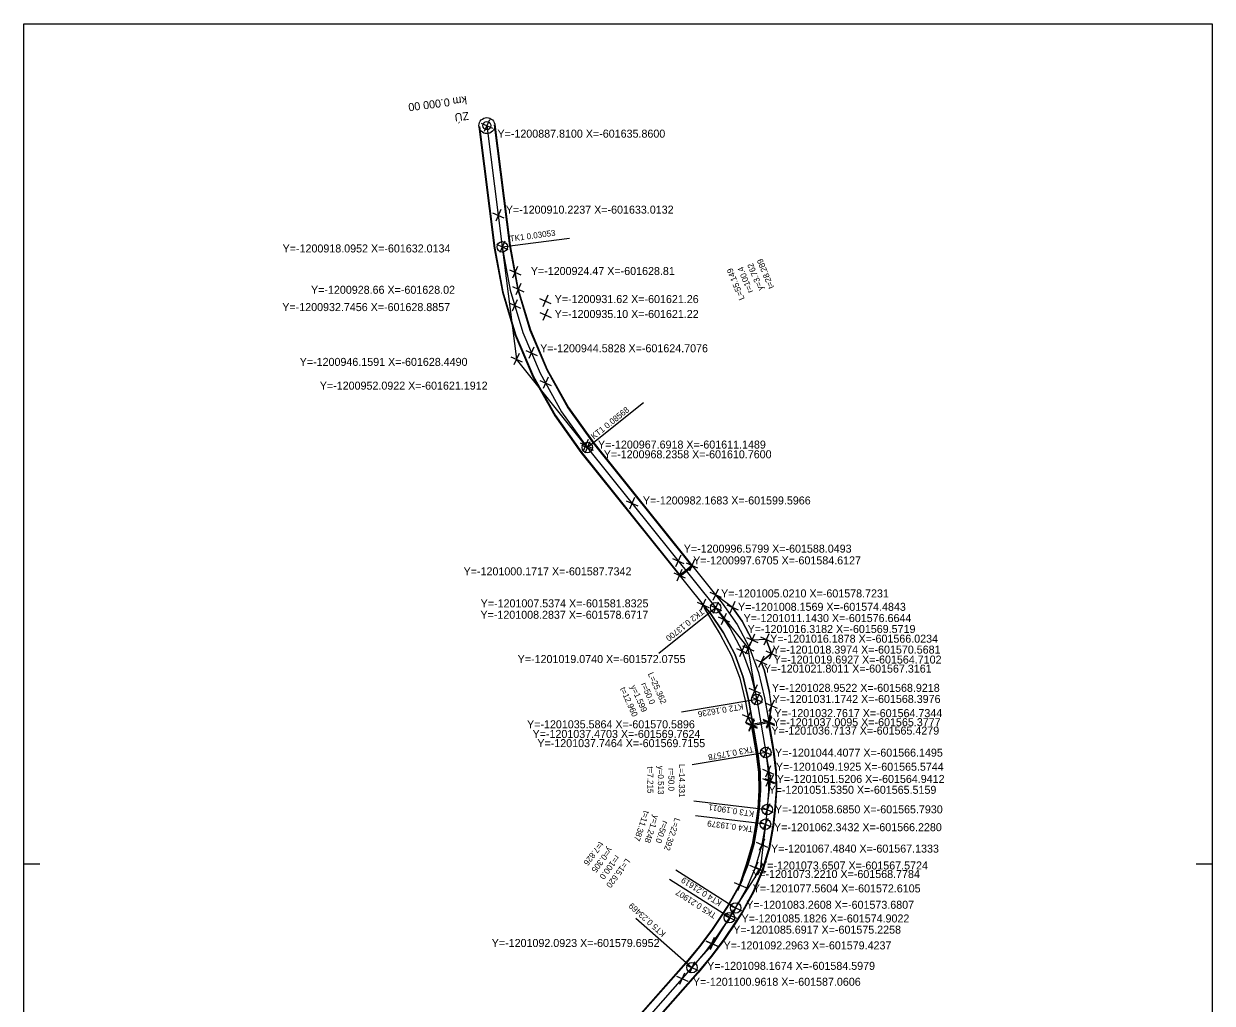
# Model space of a CAD drawing. Extents: x -601752 to -601455, y -1201912 to -1200862.
# Drawn here: x -601751.6 to -601454.6, y -1201107.1 to -1200862.4 of the extents above; entities that cross this region are included whole.
import ezdxf

# ---------------------------------------------------------------- set-up
doc = ezdxf.new("R2010")
doc.units = 0
for name, color, linetype in [('g_vytyceni oblouky', 7, 'Continuous'), ('g_vytyceni prejezd', 7, 'Continuous'), ('g_vytyceni příčné', 7, 'Continuous'), ('q_vytyceni prahy souradnice', 7, 'Continuous'), ('u_návrh', 7, 'Continuous'), ('u_oblouky', 7, 'Continuous'), ('u_osa', 7, 'Continuous'), ('u_popis', 7, 'Continuous'), ('u_popis oblouky', 7, 'Continuous'), ('u_rozšíření v obloucích', 7, 'Continuous'), ('u_staniceni', 7, 'Continuous'), ('x_rám', 7, 'Continuous')]:
    doc.layers.add(name, color=color, linetype=linetype)

msp = doc.modelspace()

# ---------------------------------------------------------------- linework, layer by layer
at = {"layer": 'g_vytyceni oblouky'}
for p, q in [((-601633.44, -1200917.46), (-601630.58, -1200918.73)), ((-601631.38, -1200916.67), (-601632.65, -1200919.52)), ((-601624.08, -1200943.15), (-601625.34, -1200946.01)), ((-601629.88, -1200945.53), (-601627.02, -1200946.79)), ((-601627.82, -1200944.73), (-601629.08, -1200947.59)), ((-601626.14, -1200943.95), (-601623.28, -1200945.22)), ((-601610.13, -1200966.81), (-601611.39, -1200969.66)), ((-601612.19, -1200967.6), (-601609.33, -1200968.87)), ((-601580.1, -1201007.65), (-601577.24, -1201008.92)), ((-601578.04, -1201006.85), (-601579.3, -1201009.71)), ((-601569.94, -1201016.97), (-601571.2, -1201019.83)), ((-601573.5, -1201018.44), (-601570.65, -1201019.71)), ((-601571.44, -1201017.65), (-601572.71, -1201020.5)), ((-601572, -1201017.76), (-601569.14, -1201019.03)), ((-601569.83, -1201030.54), (-601566.97, -1201031.81)), ((-601567.77, -1201029.75), (-601569.03, -1201032.6)), ((-601567.58, -1201043.78), (-601564.72, -1201045.04)), ((-601565.52, -1201042.98), (-601566.78, -1201045.84)), ((-601564.88, -1201050.11), (-601566.15, -1201052.96)), ((-601564.31, -1201050.09), (-601565.57, -1201052.95)), ((-601566.94, -1201050.9), (-601564.09, -1201052.17)), ((-601566.37, -1201050.89), (-601563.51, -1201052.15)), ((-601567.22, -1201058.05), (-601564.36, -1201059.32)), ((-601565.16, -1201057.26), (-601566.43, -1201060.11)), ((-601567.66, -1201061.71), (-601564.8, -1201062.98)), ((-601565.6, -1201060.91), (-601566.86, -1201063.77)), ((-601570.21, -1201072.59), (-601567.35, -1201073.85)), ((-601568.15, -1201071.79), (-601569.41, -1201074.65)), ((-601569, -1201073.02), (-601566.14, -1201074.28)), ((-601566.94, -1201072.22), (-601568.2, -1201075.08)), ((-601575.11, -1201082.63), (-601572.25, -1201083.89)), ((-601573.05, -1201081.83), (-601574.31, -1201084.69)), ((-601576.65, -1201085.06), (-601573.8, -1201086.32)), ((-601574.59, -1201084.26), (-601575.86, -1201087.12)), ((-601581.12, -1201091.46), (-601578.27, -1201092.72)), ((-601580.85, -1201091.66), (-601577.99, -1201092.93)), ((-601579.06, -1201090.66), (-601580.33, -1201093.52)), ((-601578.79, -1201090.87), (-601580.06, -1201093.73)), ((-601586.03, -1201097.53), (-601583.17, -1201098.8)), ((-601583.97, -1201096.74), (-601585.23, -1201099.6))]:
    msp.add_line(p, q, dxfattribs=at)
at = {"layer": 'g_vytyceni prejezd'}
for p, q in [((-601630.24, -1200923.84), (-601627.38, -1200925.1)), ((-601628.18, -1200923.04), (-601629.44, -1200925.9)), ((-601629.45, -1200928.03), (-601626.59, -1200929.29)), ((-601627.39, -1200927.23), (-601628.65, -1200930.09)), ((-601622.69, -1200930.98), (-601619.84, -1200932.25)), ((-601620.63, -1200930.19), (-601621.9, -1200933.04)), ((-601620.59, -1200933.67), (-601621.85, -1200936.53)), ((-601622.65, -1200934.47), (-601619.79, -1200935.73)), ((-601580.15, -1201004.39), (-601577.29, -1201005.65)), ((-601578.09, -1201003.59), (-601579.36, -1201006.45)), ((-601583.26, -1201006.9), (-601580.4, -1201008.17)), ((-601581.2, -1201006.11), (-601582.46, -1201008.97)), ((-601575.91, -1201007.52), (-601573.06, -1201008.79)), ((-601573.85, -1201006.73), (-601575.12, -1201009.59)), ((-601571, -1201015.69), (-601568.14, -1201016.95)), ((-601568.94, -1201014.89), (-601570.2, -1201017.75)), ((-601567.45, -1201015.56), (-601564.59, -1201016.82)), ((-601565.39, -1201014.76), (-601566.66, -1201017.62)), ((-601566.68, -1201020.37), (-601567.95, -1201023.23)), ((-601566.14, -1201019.06), (-601563.28, -1201020.33)), ((-601564.08, -1201018.26), (-601565.34, -1201021.12)), ((-601568.74, -1201021.17), (-601565.89, -1201022.43)), ((-601566.16, -1201032.13), (-601563.31, -1201033.39)), ((-601564.1, -1201031.33), (-601565.37, -1201034.19)), ((-601572.02, -1201034.95), (-601569.16, -1201036.22)), ((-601569.96, -1201034.16), (-601571.22, -1201037.02)), ((-601571.14, -1201037.11), (-601568.29, -1201038.38)), ((-601569.08, -1201036.32), (-601570.35, -1201039.18)), ((-601566.81, -1201036.38), (-601563.95, -1201037.64)), ((-601564.75, -1201035.58), (-601566.01, -1201038.44)), ((-601571.98, -1201076.13), (-601573.24, -1201078.99)), ((-601574.04, -1201076.93), (-601571.18, -1201078.19))]:
    msp.add_line(p, q, dxfattribs=at)
at = {"layer": 'g_vytyceni příčné'}
for p, q in [((-601635.23, -1200886.38), (-601636.49, -1200889.24)), ((-601637.29, -1200887.18), (-601634.43, -1200888.44)), ((-601634.44, -1200909.59), (-601631.58, -1200910.86)), ((-601632.38, -1200908.79), (-601633.65, -1200911.65)), ((-601628.25, -1200931.32), (-601629.52, -1200934.17)), ((-601630.31, -1200932.11), (-601627.46, -1200933.38)), ((-601622.62, -1200951.46), (-601619.76, -1200952.72)), ((-601620.56, -1200950.66), (-601621.82, -1200953.52)), ((-601610.52, -1200966.26), (-601611.78, -1200969.12)), ((-601612.58, -1200967.06), (-601609.72, -1200968.32)), ((-601601.03, -1200981.54), (-601598.17, -1200982.8)), ((-601598.96, -1200980.74), (-601600.23, -1200983.6)), ((-601589.48, -1200995.95), (-601586.62, -1200997.21)), ((-601587.42, -1200995.15), (-601588.68, -1200998.01)), ((-601578.09, -1201010.51), (-601575.24, -1201011.78)), ((-601576.03, -1201009.71), (-601577.3, -1201012.57)), ((-601570.35, -1201028.32), (-601567.49, -1201029.58)), ((-601568.29, -1201027.52), (-601569.55, -1201030.38)), ((-601567, -1201048.56), (-601564.15, -1201049.82)), ((-601564.94, -1201047.76), (-601566.21, -1201050.62)), ((-601568.56, -1201066.85), (-601565.7, -1201068.12)), ((-601566.5, -1201066.06), (-601567.77, -1201068.91)), ((-601576.33, -1201084.55), (-601573.47, -1201085.82)), ((-601574.27, -1201083.75), (-601575.53, -1201086.61)), ((-601588.49, -1201100.33), (-601585.63, -1201101.59)), ((-601586.43, -1201099.53), (-601587.69, -1201102.39))]:
    msp.add_line(p, q, dxfattribs=at)
at = {"layer": 'q_vytyceni prahy souradnice'}
for p, q in [((-601583.98, -1200996.24), (-601585.25, -1200999.1)), ((-601589.16, -1200999.54), (-601586.31, -1201000.8)), ((-601587.1, -1200998.74), (-601588.37, -1201001.6)), ((-601586.04, -1200997.04), (-601583.18, -1200998.3)), ((-601564.8, -1201035.28), (-601566.06, -1201038.14)), ((-601571.19, -1201036.84), (-601568.33, -1201038.1)), ((-601569.13, -1201036.04), (-601570.39, -1201038.9)), ((-601566.86, -1201036.08), (-601564, -1201037.35))]:
    msp.add_line(p, q, dxfattribs=at)
at = {"layer": 'u_návrh'}
for p, q in [((-601574.48, -1201008.16), (-601578.72, -1201005.02)), ((-601581.83, -1201007.54), (-601581.51, -1201008.42)), ((-601566.02, -1201016.19), (-601569.57, -1201016.32)), ((-601564.71, -1201019.69), (-601567.32, -1201021.8)), ((-601564.73, -1201032.76), (-601565.23, -1201029.47)), ((-601564.73, -1201032.76), (-601565.43, -1201036.71)), ((-601569.85, -1201036.98), (-601570.59, -1201035.59)), ((-601565.43, -1201036.71), (-601569.77, -1201037.45)), ((-601565.38, -1201037.01), (-601569.72, -1201037.75))]:
    msp.add_line(p, q, dxfattribs=at)
for points in [[(-601637.84, -1200888.06), (-601633.99, -1200918.4), (-601631.97, -1200929.41), (-601628.75, -1200940.18), (-601624.36, -1200950.53), (-601618.86, -1200960.34), (-601612.36, -1200969.44), (-601581.83, -1201007.54)], [(-601637.7, -1200888.04), (-601633.84, -1200918.38), (-601631.83, -1200929.37), (-601628.61, -1200940.13), (-601624.22, -1200950.47), (-601618.73, -1200960.26), (-601612.24, -1200969.35), (-601587.62, -1201000.08)], [(-601634.02, -1200887.58), (-601630.18, -1200917.81), (-601628.22, -1200928.51), (-601625.12, -1200938.87), (-601620.9, -1200948.83), (-601615.61, -1200958.27), (-601609.28, -1200967.12), (-601584.73, -1200997.76)], [(-601633.88, -1200887.56), (-601630.04, -1200917.79), (-601628.08, -1200928.47), (-601624.98, -1200938.82), (-601620.76, -1200948.77), (-601615.48, -1200958.19), (-601609.16, -1200967.03), (-601578.72, -1201005.02)], [(-601584.61, -1200997.67), (-601586.17, -1200998.92), (-601587.73, -1201000.17)], [(-601584.4, -1200997.94), (-601585.96, -1200999.19), (-601587.52, -1201000.44)], [(-601578.72, -1201005.02), (-601577.07, -1201007.08), (-601573.32, -1201012.42), (-601570.25, -1201018.25), (-601567.94, -1201024.42), (-601566.44, -1201030.78), (-601565.5, -1201036.27)], [(-601581.83, -1201007.54), (-601580.12, -1201009.44), (-601576.74, -1201014.51), (-601573.9, -1201019.89), (-601571.77, -1201025.59), (-601570.36, -1201031.57), (-601568.13, -1201044.7), (-601567.57, -1201049.29), (-601567.46, -1201053.88), (-601567.78, -1201058.5), (-601568.21, -1201062.05), (-601569.15, -1201067.4), (-601570.67, -1201072.55), (-601572.61, -1201077.56)], [(-601581.51, -1201008.42), (-601577.52, -1201014.97), (-601574.73, -1201020.26), (-601572.63, -1201025.85), (-601571.24, -1201031.75), (-601570.59, -1201035.59)], [(-601574.48, -1201008.16), (-601572.04, -1201011.64), (-601569.57, -1201016.32)], [(-601566.02, -1201016.19), (-601564.71, -1201019.69)], [(-601567.32, -1201021.8), (-601566.5, -1201023.99), (-601565.23, -1201029.47)], [(-601565.53, -1201037.03), (-601564.32, -1201044.14), (-601563.73, -1201049.01), (-601563.6, -1201053.96), (-601563.95, -1201058.86), (-601564.4, -1201062.61), (-601565.39, -1201068.28), (-601567.03, -1201073.84), (-601569.28, -1201079.19), (-601572.09, -1201084.21), (-601573.68, -1201086.7), (-601576.62, -1201091.08), (-601579.81, -1201095.32), (-601583.19, -1201099.37), (-601602.51, -1201121.29), (-601608.95, -1201129.42), (-601614.47, -1201138.14), (-601619.05, -1201147.4), (-601622.65, -1201157.12), (-601623.73, -1201160.61)], [(-601565.43, -1201036.71), (-601564.17, -1201044.12), (-601563.58, -1201049), (-601563.45, -1201053.97), (-601563.8, -1201058.87), (-601564.25, -1201062.63), (-601565.25, -1201068.31), (-601566.89, -1201073.89), (-601569.15, -1201079.26), (-601571.96, -1201084.29), (-601573.55, -1201086.79), (-601576.5, -1201091.17), (-601579.69, -1201095.42), (-601583.08, -1201099.47), (-601602.4, -1201121.39), (-601608.83, -1201129.51), (-601614.34, -1201138.22), (-601618.91, -1201147.46), (-601622.51, -1201157.17), (-601623.59, -1201160.65)], [(-601569.85, -1201036.98), (-601568.53, -1201044.75), (-601567.97, -1201049.32), (-601567.86, -1201053.87), (-601568.18, -1201058.46), (-601568.6, -1201061.99), (-601569.54, -1201067.3), (-601571.04, -1201072.41), (-601572.75, -1201077.5)], [(-601569.57, -1201037.72), (-601568.38, -1201044.73), (-601567.82, -1201049.31), (-601567.71, -1201053.87), (-601568.03, -1201058.47), (-601568.45, -1201062.02), (-601569.39, -1201067.34), (-601570.9, -1201072.46), (-601572.61, -1201077.56)], [(-601572.75, -1201077.5), (-601575.4, -1201082.24), (-601576.9, -1201084.6), (-601579.76, -1201088.85), (-601582.83, -1201092.93), (-601586.12, -1201096.86), (-601605.47, -1201118.82), (-601612.1, -1201127.19), (-601617.84, -1201136.26), (-601622.59, -1201145.87), (-601626.29, -1201155.88), (-601627.44, -1201159.58), (-601628.96, -1201165.79), (-601629.7, -1201172.21), (-601629.64, -1201178.67), (-601628.79, -1201185.01), (-601625.54, -1201201.39), (-601623.73, -1201208.12), (-601620.99, -1201214.62), (-601617.4, -1201220.68), (-601613.06, -1201226.15), (-601607.6, -1201232.16), (-601599.98, -1201239.49)], [(-601572.61, -1201077.56), (-601575.27, -1201082.31), (-601576.77, -1201084.68), (-601579.64, -1201088.94), (-601582.71, -1201093.02), (-601586, -1201096.96), (-601605.35, -1201118.92), (-601611.97, -1201127.28), (-601617.7, -1201136.33), (-601622.45, -1201145.93), (-601626.15, -1201155.93), (-601627.3, -1201159.62), (-601628.81, -1201165.82), (-601629.55, -1201172.22), (-601629.49, -1201178.66), (-601628.64, -1201184.99), (-601625.4, -1201201.35), (-601623.58, -1201208.08), (-601620.85, -1201214.55), (-601617.27, -1201220.6), (-601612.94, -1201226.05), (-601607.49, -1201232.05), (-601600.09, -1201239.17)]]:
    msp.add_lwpolyline(points, dxfattribs=at)
at = {"layer": 'u_oblouky'}
for p, q in [((-601632.01, -1200918.1), (-601615.18, -1200915.96)), ((-601632.01, -1200918.1), (-601628.45, -1200946.16)), ((-601610.76, -1200968.24), (-601628.45, -1200946.16)), ((-601610.76, -1200968.24), (-601596.75, -1200957.01)), ((-601578.67, -1201008.28), (-601592.89, -1201019.68)), ((-601578.67, -1201008.28), (-601570.57, -1201018.4)), ((-601568.4, -1201031.17), (-601570.57, -1201018.4)), ((-601568.4, -1201031.17), (-601587.21, -1201034.37)), ((-601566.15, -1201044.41), (-601584.54, -1201047.53)), ((-601566.15, -1201044.41), (-601564.94, -1201051.52)), ((-601565.79, -1201058.68), (-601564.94, -1201051.52)), ((-601584.11, -1201056.51), (-601565.79, -1201058.68)), ((-601566.23, -1201062.34), (-601567.57, -1201073.65)), ((-601573.68, -1201083.26), (-601567.57, -1201073.65)), ((-601575.23, -1201085.69), (-601579.42, -1201092.3)), ((-601584.6, -1201098.17), (-601579.42, -1201092.3))]:
    msp.add_line(p, q, dxfattribs=at)
for points in [[(-601566.23, -1201062.34), (-601583.73, -1201060.26)], [(-601588.6, -1201073.78), (-601573.68, -1201083.26)], [(-601575.23, -1201085.69), (-601590.18, -1201076.19)], [(-601598.64, -1201085.79), (-601584.6, -1201098.17)]]:
    msp.add_lwpolyline(points, dxfattribs=at)
for centre in [(-601632.01, -1200918.1), (-601610.76, -1200968.24), (-601578.67, -1201008.28), (-601568.4, -1201031.17), (-601566.15, -1201044.41), (-601565.79, -1201058.68), (-601566.23, -1201062.34), (-601573.68, -1201083.26), (-601575.23, -1201085.69), (-601584.6, -1201098.17)]:
    msp.add_circle(centre, 1.31, dxfattribs=at)
at = {"layer": 'u_osa'}
msp.add_lwpolyline([(-601635.86, -1200887.81), (-601632.01, -1200918.1), (-601630.03, -1200928.94), (-601626.86, -1200939.5), (-601622.56, -1200949.65), (-601617.17, -1200959.27), (-601610.76, -1200968.24), (-601578.67, -1201008.28), (-601575.03, -1201013.47), (-601572.08, -1201019.07), (-601569.85, -1201025.01), (-601568.4, -1201031.17), (-601566.15, -1201044.41), (-601565.58, -1201049.15), (-601565.46, -1201053.92), (-601565.79, -1201058.68), (-601566.23, -1201062.34), (-601567.2, -1201067.85), (-601568.78, -1201073.22), (-601570.95, -1201078.38), (-601573.68, -1201083.26), (-601575.23, -1201085.69), (-601578.13, -1201090.01), (-601581.26, -1201094.17), (-601584.6, -1201098.17), (-601603.93, -1201120.11)], dxfattribs=at)
at = {"layer": 'u_rozšíření v obloucích'}
for points in [[(-601565.43, -1201036.71), (-601564.73, -1201032.76), (-601565.23, -1201029.47), (-601566.5, -1201023.99), (-601567.32, -1201021.8), (-601564.71, -1201019.69), (-601566.02, -1201016.19), (-601569.57, -1201016.32), (-601572.04, -1201011.64), (-601574.48, -1201008.16), (-601578.72, -1201005.02), (-601577.07, -1201007.08), (-601573.32, -1201012.42), (-601570.25, -1201018.25), (-601567.94, -1201024.42), (-601566.44, -1201030.78), (-601565.43, -1201036.71)], [(-601580.12, -1201009.44), (-601581.33, -1201008.1), (-601581.83, -1201007.54), (-601581.51, -1201008.42), (-601580.5, -1201010.07), (-601579.1, -1201012.37), (-601578.16, -1201013.92), (-601577.52, -1201014.97), (-601574.73, -1201020.26), (-601572.63, -1201025.85), (-601571.24, -1201031.75), (-601570.59, -1201035.59), (-601569.85, -1201036.98), (-601569.72, -1201037.75), (-601569.57, -1201037.72), (-601568.38, -1201044.73), (-601567.82, -1201049.31), (-601567.71, -1201053.87), (-601568.03, -1201058.47), (-601568.45, -1201062.02), (-601569.39, -1201067.34), (-601570.9, -1201072.46), (-601572.61, -1201077.56), (-601570.67, -1201072.55), (-601569.15, -1201067.4), (-601568.21, -1201062.05), (-601567.78, -1201058.5), (-601567.46, -1201053.88), (-601567.57, -1201049.29), (-601568.13, -1201044.7), (-601570.36, -1201031.57), (-601571.77, -1201025.59), (-601573.9, -1201019.89), (-601576.74, -1201014.51), (-601580.12, -1201009.44)]]:
    msp.add_lwpolyline(points, dxfattribs=at)
at = {"layer": 'u_staniceni'}
for radius in [2, 1]:
    msp.add_circle((-601635.86, -1200887.81), radius, dxfattribs=at)
at = {"layer": 'x_rám'}
for p, q in [((-601747.54, -1201072.35), (-601751.58, -1201072.35)), ((-601454.58, -1201072.35), (-601458.63, -1201072.35))]:
    msp.add_line(p, q, dxfattribs=at)
msp.add_lwpolyline([(-601454.58, -1200862.35), (-601454.58, -1201912.35), (-601751.58, -1201912.35), (-601751.58, -1200862.35)], close=True, dxfattribs=at)

# ---------------------------------------------------------------- texts
at = {"layer": 'g_vytyceni oblouky'}
for s, p in [('Y=-1200918.0952 X=-601632.0134', (-601686.9, -1200919.49)), ('Y=-1200944.5828 X=-601624.7076', (-601622.54, -1200944.43)), ('Y=-1200946.1591 X=-601628.4490', (-601682.63, -1200947.83)), ('Y=-1200968.2358 X=-601610.7600', (-601606.64, -1200970.92)), ('Y=-1201008.2837 X=-601578.6717', (-601637.46, -1201011.01)), ('Y=-1201019.0740 X=-601572.0755', (-601628.16, -1201022.08)), ('Y=-1201018.3974 X=-601570.5681', (-601564.42, -1201019.72)), ('Y=-1201031.1742 X=-601568.3976', (-601564.42, -1201032.05)), ('Y=-1201044.4077 X=-601566.1495', (-601563.85, -1201045.46)), ('Y=-1201051.5206 X=-601564.9412', (-601563.41, -1201052.03)), ('Y=-1201051.5350 X=-601565.5159', (-601565.46, -1201054.75)), ('Y=-1201058.6850 X=-601565.7930', (-601563.87, -1201059.63)), ('Y=-1201062.3432 X=-601566.2280', (-601564.1, -1201064.09)), ('Y=-1201073.2210 X=-601568.7784', (-601569.58, -1201075.79)), ('Y=-1201073.6507 X=-601567.5724', (-601567.57, -1201073.65)), ('Y=-1201083.2608 X=-601573.6807', (-601571.03, -1201083.47)), ('Y=-1201085.6917 X=-601575.2258', (-601574.3, -1201089.69)), ('Y=-1201092.0923 X=-601579.6952', (-601634.64, -1201093.02)), ('Y=-1201092.2963 X=-601579.4237', (-601576.7, -1201093.62)), ('Y=-1201098.1674 X=-601584.5979', (-601580.79, -1201098.73))]:
    msp.add_text(s, height=2, dxfattribs=at).set_placement(p)
at = {"layer": 'g_vytyceni prejezd'}
for s, p in [('Y=-1200924.47 X=-601628.81', (-601624.88, -1200925.13)), ('Y=-1200928.66 X=-601628.02', (-601679.8, -1200929.82)), ('Y=-1200931.62 X=-601621.26', (-601618.91, -1200932.14)), ('Y=-1200935.10 X=-601621.22', (-601618.91, -1200935.86)), ('Y=-1201005.0210 X=-601578.7231', (-601577.33, -1201005.68)), ('Y=-1201007.5374 X=-601581.8325', (-601637.41, -1201008.17)), ('Y=-1201008.1569 X=-601574.4843', (-601573.09, -1201009.03)), ('Y=-1201016.3182 X=-601569.5719', (-601570.69, -1201014.57)), ('Y=-1201016.1878 X=-601566.0234', (-601565.05, -1201016.99)), ('Y=-1201019.6927 X=-601564.7102', (-601564.17, -1201022.21)), ('Y=-1201021.8011 X=-601567.3161', (-601566.64, -1201024.47)), ('Y=-1201032.7617 X=-601564.7344', (-601564, -1201035.59)), ('Y=-1201035.5864 X=-601570.5896', (-601625.82, -1201038.38)), ('Y=-1201036.7137 X=-601565.4279', (-601564.76, -1201039.96)), ('Y=-1201037.7464 X=-601569.7155', (-601623.24, -1201043.09)), ('Y=-1201077.5604 X=-601572.6105', (-601569.4, -1201079.38))]:
    msp.add_text(s, height=2, dxfattribs=at).set_placement(p)
at = {"layer": 'g_vytyceni příčné'}
for s, p in [('Y=-1200887.8100 X=-601635.8600', (-601633.21, -1200890.81)), ('Y=-1200910.2237 X=-601633.0132', (-601631.13, -1200909.8)), ('Y=-1200932.7456 X=-601628.8857', (-601686.98, -1200934.14)), ('Y=-1200952.0922 X=-601621.1912', (-601677.61, -1200953.77)), ('Y=-1200967.6918 X=-601611.1489', (-601608.08, -1200968.49)), ('Y=-1200982.1683 X=-601599.5966', (-601596.87, -1200982.45)), ('Y=-1200996.5799 X=-601588.0493', (-601586.65, -1200994.49)), ('Y=-1201011.1430 X=-601576.6644', (-601571.71, -1201011.84)), ('Y=-1201028.9522 X=-601568.9218', (-601564.63, -1201029.27)), ('Y=-1201049.1925 X=-601565.5744', (-601563.62, -1201048.98)), ('Y=-1201067.4840 X=-601567.1333', (-601564.83, -1201069.44)), ('Y=-1201085.1826 X=-601574.9022', (-601572.21, -1201086.89)), ('Y=-1201100.9618 X=-601587.0606', (-601584.37, -1201102.71))]:
    msp.add_text(s, height=2, dxfattribs=at).set_placement(p)
at = {"layer": 'q_vytyceni prahy souradnice'}
for s, p in [('Y=-1200997.6705 X=-601584.6127', (-601584.3, -1200997.43)), ('Y=-1201000.1717 X=-601587.7342', (-601641.67, -1201000.17)), ('Y=-1201037.0095 X=-601565.3777', (-601564.4, -1201037.85)), ('Y=-1201037.4703 X=-601569.7624', (-601624.44, -1201040.79))]:
    msp.add_text(s, height=2, dxfattribs=at).set_placement(p)
at = {"layer": 'u_oblouky'}
for s, rotation, p in [('y=3.762', 112.0629, (-601566.72, -1200928.66)), ('t=28.289', 112.0629, (-601564.07, -1200928.2)), ('L=55.149', 112.0629, (-601571.41, -1200931.06)), ('r=100.4', 112.0629, (-601569.3, -1200929.26)), ('L=25.362', 294.0548, (-601595.68, -1201024.78)), ('t=12.960', 294.0548, (-601602.64, -1201028.49)), ('y=1.599', 294.0548, (-601600.02, -1201027.94)), ('r=50.0', 294.0548, (-601597.41, -1201027.34)), ('t=7.215', 270, (-601595.74, -1201047.9)), ('y=0.513', 270, (-601593.12, -1201047.73)), ('r=50.0', 270, (-601590.49, -1201048.3)), ('L=14.331', 270, (-601587.87, -1201047.26)), ('t=11.387', 251.047, (-601596.58, -1201058.83)), ('y=1.248', 251.047, (-601594.17, -1201059.89)), ('r=50.0', 251.047, (-601591.89, -1201061.32)), ('L=22.392', 251.047, (-601588.88, -1201060.64)), ('t=7.826', 233.2283, (-601607.75, -1201066.54)), ('y=0.305', 233.2283, (-601605.53, -1201067.96)), ('r=100.0', 233.2283, (-601603.71, -1201069.91)), ('L=15.620', 233.2283, (-601601.09, -1201070.78))]:
    msp.add_text(s, height=1.5, rotation=rotation, dxfattribs=at).set_placement(p)
at = {"layer": 'u_popis'}
for s, p in [('km 0.000 00', (-601640.99, -1200880.38)), ('ZÚ', (-601640.48, -1200884.35))]:
    msp.add_text(s, height=2, rotation=187.2385, dxfattribs=at).set_placement(p)
at = {"layer": 'u_popis oblouky'}
for s, rotation, p in [('TK1 0.03053', 7.7303, (-601630.02, -1200916.82)), ('KT1 0.08568', 38.7034, (-601609.1, -1200966.27)), ('TK2 0.13700', 218.7034, (-601582.33, -1201008.43)), ('KT2 0.16236', 189.7278, (-601571.9, -1201032.2)), ('TK3 0.17578', 190.4595, (-601569.36, -1201042.85)), ('KT3 0.19011', 171.2696, (-601569, -1201059.08)), ('TK4 0.19379', 172.473, (-601569.28, -1201062.89)), ('KT4 0.21619', 147.3685, (-601577.01, -1201081.67)), ('TK5 0.21907', 147.5404, (-601578.35, -1201084.73)), ('KT5 0.23469', 138.1127, (-601591.03, -1201089.53))]:
    msp.add_text(s, height=1.5, rotation=rotation, dxfattribs=at).set_placement(p)

doc.saveas('drawing.dxf')
